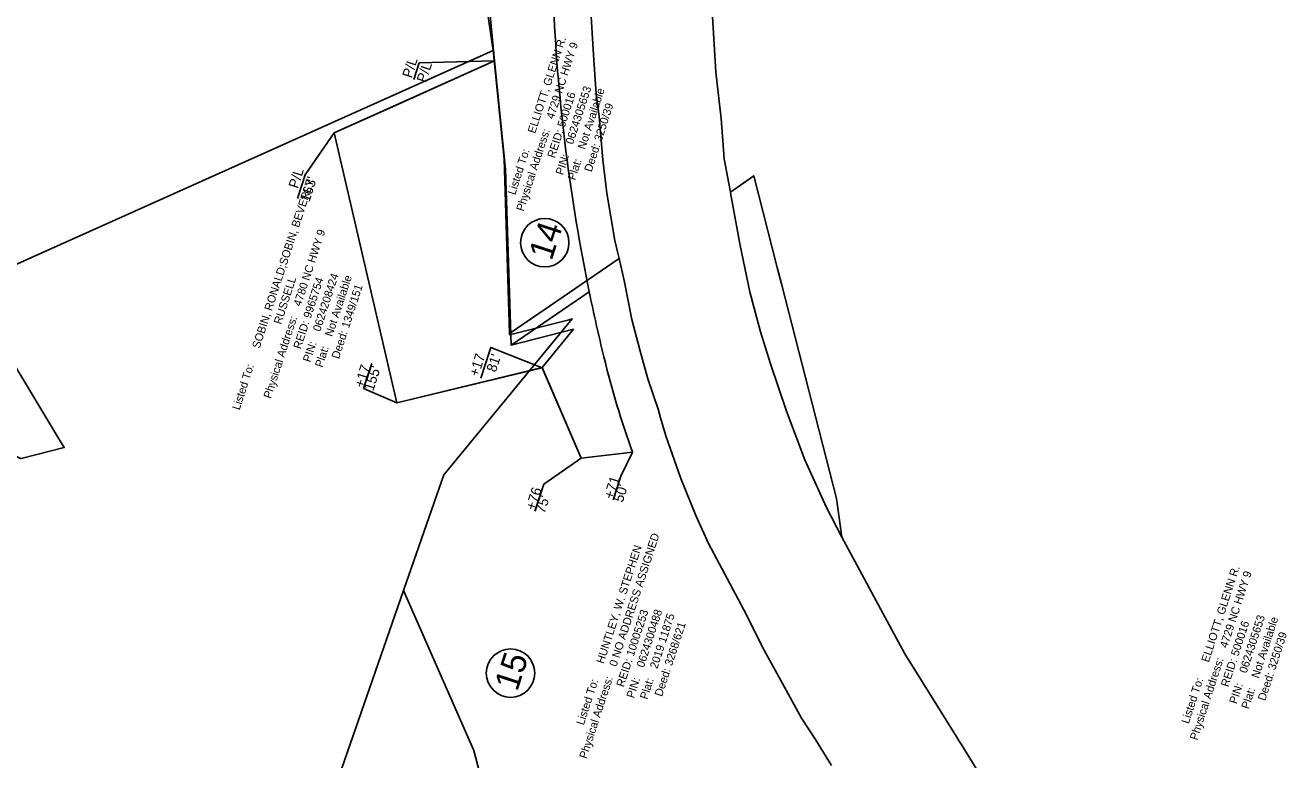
# Model space of a CAD drawing. Extents: x 1019969 to 1024963, y 638146 to 643978.
# Drawn here: x 1022801 to 1023426, y 640385 to 640749 of the extents above; entities that cross this region are included whole.
import ezdxf

# ---------------------------------------------------------------- set-up
doc = ezdxf.new("R2010")
doc.units = 0
for name, color, linetype in [('Old_Level_30', 7, 'Continuous'), ('Pattern 5', 7, 'Continuous'), ('Pattern 6', 7, 'Continuous'), ('Prop Easement Construction', 7, 'Continuous'), ('Prop Easement Construction Station Offsets', 7, 'Continuous'), ('Prop Parcel Number CELL', 7, 'Continuous'), ('Prop Parcel Owner Text', 7, 'Continuous'), ('Prop ROW RW Lines', 7, 'Continuous')]:
    doc.layers.add(name, color=color, linetype=linetype)

msp = doc.modelspace()

# ---------------------------------------------------------------- linework, layer by layer
at = {"layer": 'Old_Level_30'}
for points in [[(1023055.36, 640605.4), (1023041.41, 640595.86), (1023038.8, 640682.3), (1023033.32, 640736.02), (1023022.08, 640812.39), (1023008.43, 640902.89), (1023012.66, 640899.52), (1023022.6, 640884.5), (1023053.35, 640805.87), (1023062.14, 640789.09), (1023065.25, 640784.66), (1023075.54, 640770), (1023081.17, 640764.56), (1023081.43, 640758.68), (1023081.46, 640758.27), (1023083.03, 640733.83), (1023084.28, 640714.36), (1023085.72, 640703.43), (1023087.55, 640681.83), (1023089.55, 640665.32), (1023093.54, 640641.91), (1023094.86, 640636.35), (1023095.68, 640632.94)], [(1023203.44, 640514.19), (1023206.1, 640495.03), (1023198.35, 640509.67), (1023187.76, 640533.37), (1023178.57, 640557.34), (1023170.74, 640580.85), (1023165.65, 640596.66), (1023161.39, 640612.79), (1023161.19, 640613.61), (1023160.66, 640615.63), (1023155.51, 640640.35), (1023151.77, 640661.15), (1023151.11, 640664.59), (1023150.86, 640665.93), (1023162.35, 640673.99), (1023174.05, 640628.49), (1023176.11, 640620.49)]]:
    msp.add_lwpolyline(points, close=True, dxfattribs=at)
for points in [[(1023297.29, 640340.1), (1023265.41, 640391.98), (1023263.51, 640395.02), (1023263.47, 640395.09), (1023237.25, 640437.14), (1023221.86, 640465.61), (1023212.4, 640483.15), (1023206.1, 640495.03), (1023203.44, 640514.19), (1023176.11, 640620.49), (1023174.05, 640628.49), (1023162.35, 640673.99), (1023150.86, 640665.93), (1023150.06, 640670.1), (1023147.74, 640682.31), (1023146.2, 640702.28), (1023144.69, 640715.29), (1023143.52, 640725.34), (1023141.45, 640761.25)], [(1022689.3, 640373.74), (1022582.7, 640434.06), (1022575.85, 640437.94), (1022732.42, 640567.9), (1022799.18, 640534), (1022799.5, 640533.97), (1022820.81, 640539.36), (1022819.48, 640541.58), (1022817.68, 640544.57), (1022772.71, 640619.2), (1022804.56, 640633.48), (1023033.32, 640736.02), (1023038.8, 640682.3), (1023041.41, 640595.86), (1023041.43, 640595.23), (1023070.93, 640602.69), (1023072.46, 640603.07), (1023008.79, 640525.95), (1023005.32, 640515.98), (1022988.86, 640468.59), (1022949.84, 640356.28)], [(1023040.68, 640324.2), (1023023.75, 640389.4), (1022988.86, 640468.59), (1023005.32, 640515.98), (1023008.79, 640525.95), (1023072.46, 640603.07), (1023070.93, 640602.69), (1023041.43, 640595.23), (1023041.41, 640595.86), (1023055.36, 640605.4), (1023095.68, 640632.94), (1023098.25, 640622.14), (1023102.02, 640602.76), (1023106.03, 640587.78), (1023109.97, 640573.49), (1023115.15, 640557.95), (1023116.27, 640554.16), (1023118.91, 640545.25), (1023126.32, 640524), (1023133.73, 640505.74), (1023139.92, 640491.81), (1023147.82, 640476.99), (1023158.74, 640456.51), (1023166.71, 640440.59), (1023176.66, 640422.57), (1023185.97, 640405.43), (1023192.92, 640394.84), (1023192.98, 640394.75), (1023200.95, 640381.96)]]:
    msp.add_lwpolyline(points, dxfattribs=at)
at = {"layer": 'Pattern 6'}
for p, q in [((1023031.59, 640755.22), (1023034.01, 640730.95)), ((1023034.01, 640730.95), (1022985.26, 640709.01)), ((1023039.38, 640677.08), (1023034.01, 640730.95)), ((1023034.01, 640730.95), (1023039.38, 640677.08)), ((1022985.26, 640709.01), (1022954.59, 640695.2)), ((1022954.59, 640695.2), (1022985.61, 640561.55)), ((1023042.13, 640590.08), (1023039.38, 640677.08)), ((1023039.38, 640677.08), (1023042.13, 640590.08)), ((1023080.91, 640616.45), (1023042.13, 640590.08)), ((1023042.13, 640590.08), (1023080.91, 640616.45)), ((1023042.13, 640590.08), (1023073.14, 640597.97)), ((1023073.14, 640597.97), (1023042.13, 640590.08)), ((1023073.14, 640597.97), (1023057.53, 640579.01)), ((1023057.53, 640579.01), (1023073.14, 640597.97)), ((1022985.61, 640561.55), (1023057.53, 640579.01)), ((1023057.53, 640579.01), (1023076.87, 640534.14)), ((1023076.87, 640534.14), (1023102.35, 640537.03))]:
    msp.add_line(p, q, dxfattribs=at)
for centre, radius, start, end in [((1023968.6, 640799.49), 906.36, 182.70435, 191.65074), ((1023970.9, 640799.77), 908.67, 191.63935, 193.71972), ((1023543.71, 640695.48), 468.94, 193.71972, 199.74925)]:
    msp.add_arc(centre, radius, start, end, dxfattribs=at)
at = {"layer": 'Prop Easement Construction'}
for p, q in [((1023034.01, 640730.95), (1023031.59, 640755.22)), ((1023034.01, 640730.95), (1023031.59, 640755.22)), ((1022954.59, 640695.2), (1023034.01, 640730.95)), ((1022985.61, 640561.55), (1022954.59, 640695.2)), ((1023057.54, 640578.94), (1022985.61, 640561.55)), ((1023076.87, 640534.14), (1023057.54, 640578.94)), ((1023076.87, 640534.14), (1023102.35, 640537.03))]:
    msp.add_line(p, q, dxfattribs=at)
at = {"layer": 'Prop Easement Construction Station Offsets'}
for p, q in [((1022996.7, 640729.88), (1022994.05, 640721.75)), ((1022940.28, 640675.02), (1022936.28, 640662.72)), ((1023031.44, 640586.99), (1023027.15, 640573.79)), ((1022973.11, 640580.95), (1022969.08, 640568.58)), ((1023096.49, 640525.17), (1023092.68, 640513.45)), ((1023058.31, 640521.32), (1023053.96, 640507.95))]:
    msp.add_line(p, q, dxfattribs=at)
for points in [[(1022996.7, 640729.88), (1023034.01, 640730.95)], [(1022940.52, 640674.95), (1022954.59, 640695.2)], [(1023031.44, 640586.99), (1023032.08, 640588.95), (1023057.54, 640578.94)], [(1022969.08, 640568.58), (1022985.61, 640561.55)], [(1023096.49, 640525.17), (1023102.35, 640537.03)], [(1023058.31, 640521.32), (1023076.87, 640534.14)]]:
    msp.add_lwpolyline(points, dxfattribs=at)
at = {"layer": 'Prop Parcel Number CELL'}
for p, q in [((1023058.85, 640640.84), (1023058.85, 640640.84)), ((1023041.9, 640427.67), (1023041.9, 640427.67))]:
    msp.add_line(p, q, dxfattribs=at)
for centre in [(1023058.85, 640640.84), (1023041.9, 640427.67)]:
    msp.add_circle(centre, 12, dxfattribs=at)
at = {"layer": 'Prop ROW RW Lines'}
msp.add_arc((1022167.9, 640774.19), 948.09, 40.00236, 40.00236, dxfattribs=at)

# ---------------------------------------------------------------- texts
at = {"layer": 'Pattern 5'}
for s, p in [('ELLIOTT, GLENN R.', (1023054.06, 640694.66)), ('4729 NC HWY 9', (1023063.2, 640701.75)), ('0624305653', (1023072.81, 640689.28)), ('Not Available', (1023078.82, 640686.74)), ('500016', (1023068.71, 640697.69)), ('3250/39', (1023086.98, 640690.81)), ('Physical Address:', (1023048.36, 640656.11)), ('REID:', (1023063.77, 640682.47)), ('Listed To:', (1023044.17, 640664.23)), ('Deed:', (1023082.04, 640675.59)), ('PIN:', (1023067.87, 640674.06)), ('Plat:', (1023073.88, 640671.52)), ('SOBIN, RONALD;SOBIN, BEVERLY ', (1022917.53, 640588.13)), ('4780 NC HWY 9', (1022937.99, 640609.03)), ('RUSSELL', (1022928.26, 640600.11)), ('9965754', (1022942.9, 640603.1)), ('0624208424', (1022947.62, 640596.58)), ('Not Available', (1022953.62, 640594.01)), ('1349/151', (1022961.82, 640598.21)), ('Physical Address:', (1022923.15, 640563.38)), ('REID:', (1022937.95, 640587.88)), ('PIN:', (1022942.67, 640581.36)), ('Deed:', (1022956.87, 640583)), ('Plat:', (1022948.67, 640578.8)), ('Listed To:', (1022907.63, 640557.69)), ('0 NO ADDRESS ASSIGNED', (1023094.42, 640430.63)), ('HUNTLEY, W. STEPHEN', (1023088.05, 640432.06)), ('ELLIOTT, GLENN R.', (1023387.79, 640432.74)), ('4729 NC HWY 9', (1023396.93, 640439.84)), ('10005253', (1023102.91, 640435.71)), ('0624300488', (1023107.94, 640430.16)), ('2019 11875', (1023114.59, 640429.58)), ('0624305653', (1023406.55, 640427.36)), ('Not Available', (1023412.56, 640424.82)), ('3268/621', (1023121.88, 640430.98)), ('500016', (1023402.45, 640435.77)), ('3250/39', (1023420.71, 640428.89)), ('Physical Address:', (1023382.09, 640394.19)), ('REID:', (1023097.96, 640420.49)), ('Deed:', (1023116.93, 640415.77)), ('REID:', (1023397.5, 640420.55)), ('Listed To:', (1023078.16, 640401.63)), ('Physical Address:', (1023079.58, 640384.98)), ('PIN:', (1023102.99, 640414.94)), ('Plat:', (1023109.64, 640414.37)), ('Listed To:', (1023377.9, 640402.31)), ('PIN:', (1023401.6, 640412.14)), ('Deed:', (1023415.77, 640413.67)), ('Plat:', (1023407.61, 640409.6))]:
    msp.add_text(s, height=4, rotation=71.9892, dxfattribs=at).set_placement(p)
at = {"layer": 'Prop Easement Construction Station Offsets'}
for s, rotation, p in [('P/L', 71.9892, (1022992.85, 640722.08)), ('P/L', 71.9892, (1022999.98, 640719.77)), ('P/L', 71.9892, (1022936.48, 640667.37)), ("163'", 71.9892, (1022942.21, 640660.74)), ('+17', 71.9892, (1023025.95, 640574.14)), ("81'", 71.9892, (1023034.56, 640576.38)), ('+17', 71.99034, (1022969.06, 640568.59)), ("155'", 71.99034, (1022973.86, 640567.03)), ('+71', 71.99034, (1023092.66, 640513.46)), ('+76', 71.99034, (1023053.94, 640507.96)), ("50'", 71.99034, (1023097.46, 640511.89)), ("75'", 71.99034, (1023058.74, 640506.4))]:
    msp.add_text(s, height=5, rotation=rotation, dxfattribs=at).set_placement(p)
at = {"layer": 'Prop Parcel Owner Text'}
for s, p in [('14', (1023062.21, 640631.51)), ('15', (1023045.21, 640418.2))]:
    msp.add_text(s, height=12.15, rotation=71.9892, dxfattribs=at).set_placement(p)

doc.saveas('drawing.dxf')
